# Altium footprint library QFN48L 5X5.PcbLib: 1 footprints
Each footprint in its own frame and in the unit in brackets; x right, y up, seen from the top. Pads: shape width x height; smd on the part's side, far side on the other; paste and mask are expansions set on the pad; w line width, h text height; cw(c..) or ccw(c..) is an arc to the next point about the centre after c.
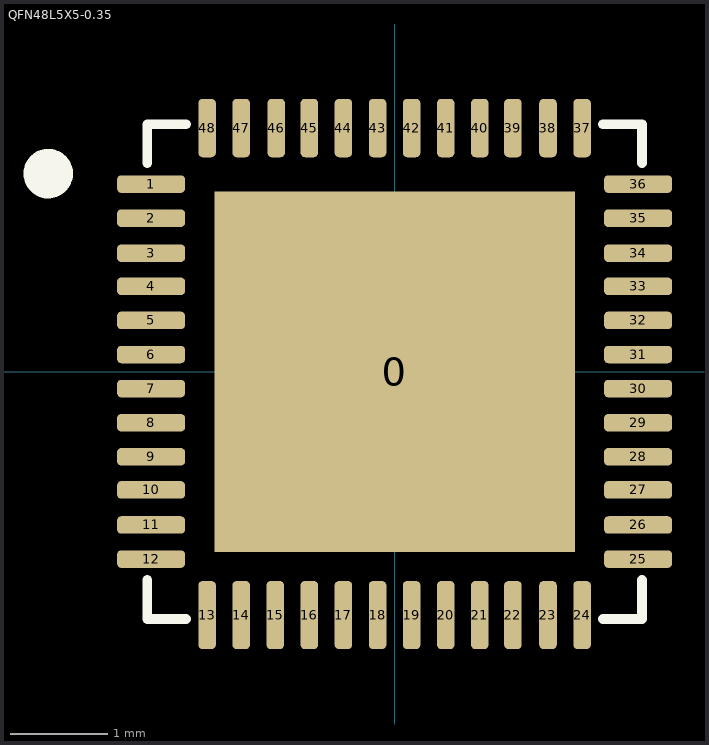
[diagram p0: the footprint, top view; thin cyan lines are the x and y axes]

## QFN48L5X5-0.35 [mm]
pads (49):
  rect 3.7x3.7 smd: 0(0,0)
  rrect50% 0.7x0.18 smd: 1(-2.5,1.925) 2(-2.5,1.575) 3(-2.5,1.215) 4(-2.5,0.875) 5(-2.5,0.525) 6(-2.5,0.175) 7(-2.5,-0.175) 8(-2.5,-0.525) 9(-2.5,-0.875) 10(-2.5,-1.215) 11(-2.5,-1.575) 12(-2.5,-1.925) 25(2.5,-1.925) 26(2.5,-1.575) 27(2.5,-1.215) 28(2.5,-0.875) 29(2.5,-0.525) 30(2.5,-0.175) 31(2.5,0.175) 32(2.5,0.525) 33(2.5,0.875) 34(2.5,1.215) 35(2.5,1.575) 36(2.5,1.925)
  rrect50% 0.18x0.7 smd: 13(-1.925,-2.5) 14(-1.575,-2.5) 15(-1.225,-2.5) 16(-0.875,-2.5) 17(-0.525,-2.5) 18(-0.175,-2.5) 19(0.175,-2.5) 20(0.525,-2.5) 21(0.875,-2.5) 22(1.215,-2.5) 23(1.575,-2.5) 24(1.925,-2.5)
  rrect50% 0.18x0.6 smd: 37(1.925,2.5) 38(1.575,2.5) 39(1.215,2.5) 40(0.875,2.5) 41(0.525,2.5) 42(0.175,2.5) 43(-0.175,2.5) 44(-0.525,2.5) 45(-0.875,2.5) 46(-1.215,2.5) 47(-1.575,2.5) 48(-1.925,2.5)
Top Overlay:
  circle w0.254: c-3.556,2.032 r0.127
  lines w0.1: -2.54,-2.14 -2.54,-2.54 -2.14,-2.54 ; -2.54,2.14 -2.54,2.54 -2.14,2.54 ; 2.14,-2.54 2.54,-2.54 2.54,-2.14 ; 2.14,2.54 2.54,2.54 2.54,2.14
